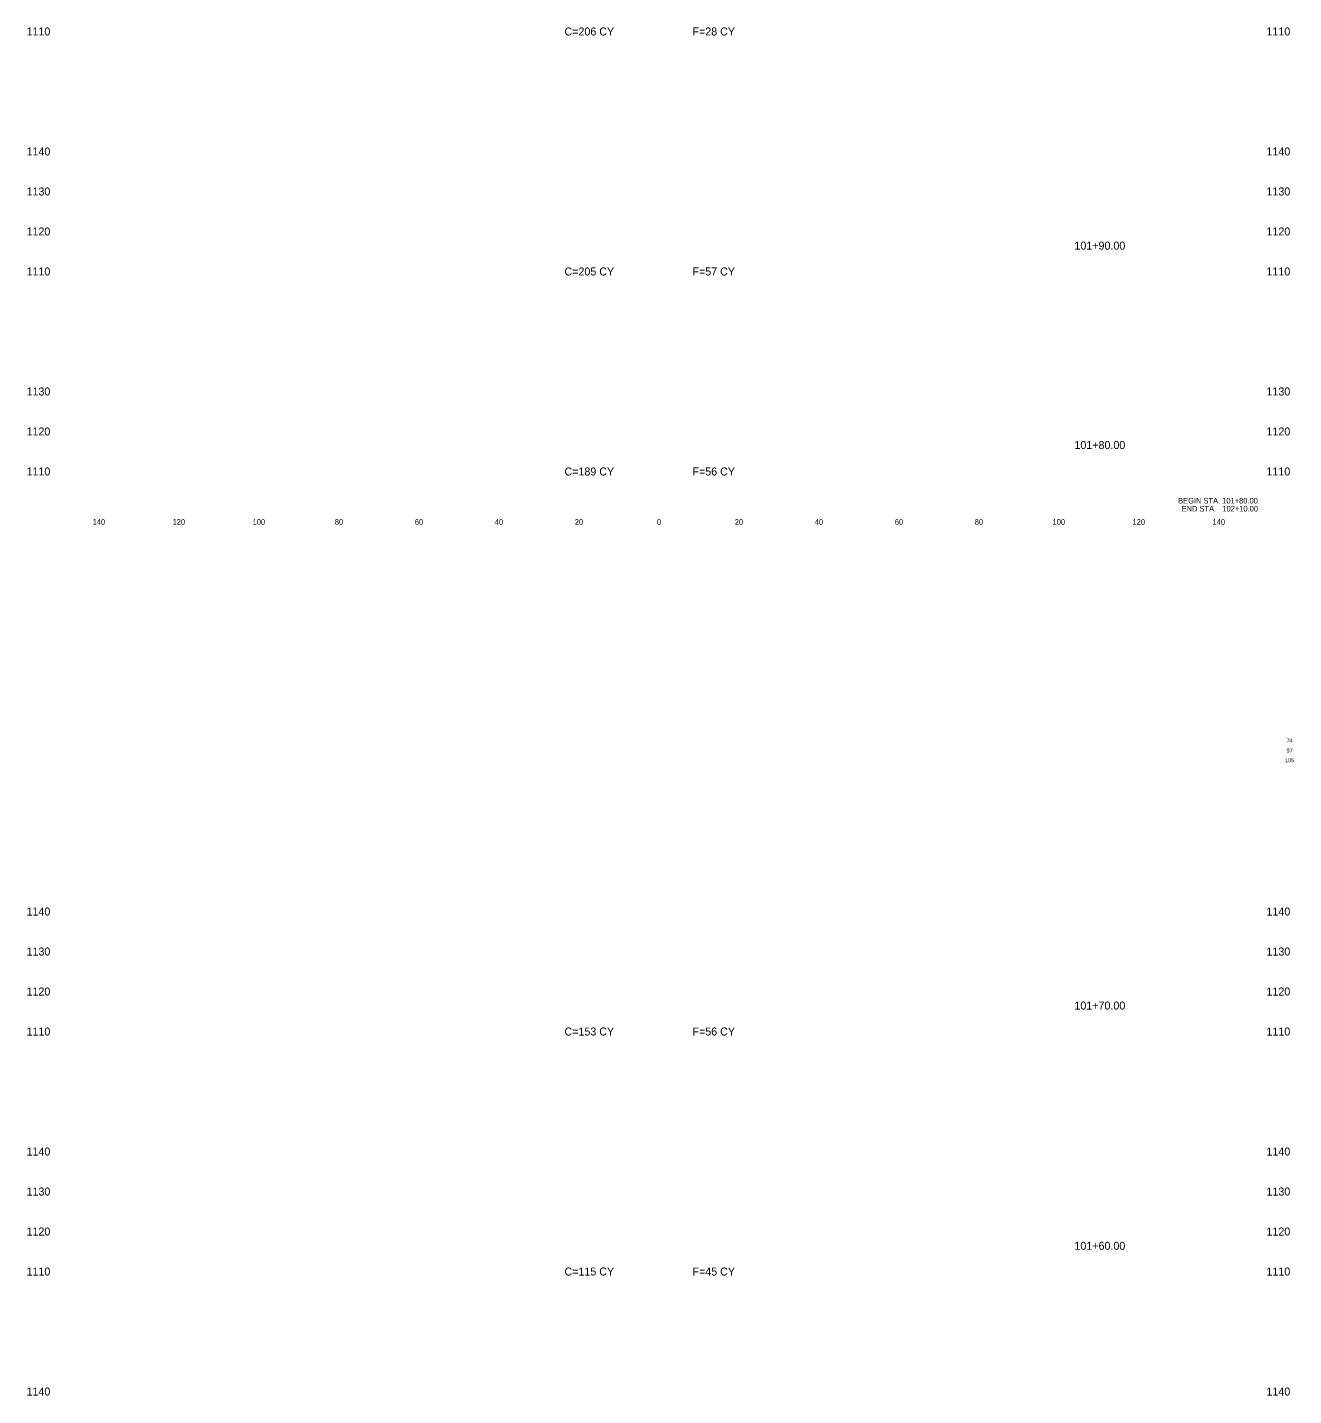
# Model space of a CAD drawing. Extents: x -200 to 1319, y -200 to 2499.
# Drawn here: x 1001.9 to 1318.5, y 1820 to 2162 of the extents above; entities that cross this region are included whole.
import ezdxf

# ---------------------------------------------------------------- set-up
doc = ezdxf.new("R2010")
doc.units = 0
for name, color, linetype in [('Default', 7, 'Continuous'), ('DESIGN - SHEET - Corner Text', 7, 'Continuous'), ('DESIGN - TYPICAL - Text', 7, 'Continuous')]:
    doc.layers.add(name, color=color, linetype=linetype)

msp = doc.modelspace()

# ---------------------------------------------------------------- texts
at = {"layer": 'Default'}
for s, height, p in [('     1110     ', 2, (998.01, 2160)), ('     1110     ', 2, (1308.01, 2160)), ('     1140     ', 2, (998.01, 2130)), ('     1140     ', 2, (1308.01, 2130)), ('     1130     ', 2, (998.01, 2120)), ('     1130     ', 2, (1308.01, 2120)), ('     1120     ', 2, (998.01, 2110)), ('     1120     ', 2, (1308.01, 2110)), ('     101+90.00     ', 2, (1260, 2106.47)), ('     1110     ', 2, (998.01, 2100)), ('     1110     ', 2, (1308.01, 2100)), ('     1130     ', 2, (998.01, 2070)), ('     1130     ', 2, (1308.01, 2070)), ('     1120     ', 2, (998.01, 2060)), ('     1120     ', 2, (1308.01, 2060)), ('     101+80.00     ', 2, (1260, 2056.62)), ('     1110     ', 2, (998.01, 2050)), ('     1110     ', 2, (1308.01, 2050)), ('     140     ', 1.4, (1015.65, 2037.7)), ('     120     ', 1.4, (1035.65, 2037.7)), ('     100     ', 1.4, (1055.65, 2037.7)), ('     80     ', 1.4, (1076.2, 2037.7)), ('     60     ', 1.4, (1096.2, 2037.7)), ('     40     ', 1.4, (1116.2, 2037.7)), ('     20     ', 1.4, (1136.2, 2037.7)), ('     0     ', 1.4, (1156.74, 2037.7)), ('     0     ', 1.4, (1156.74, 2037.7)), ('     20     ', 1.4, (1176.2, 2037.7)), ('     40     ', 1.4, (1196.2, 2037.7)), ('     60     ', 1.4, (1216.2, 2037.7)), ('     80     ', 1.4, (1236.2, 2037.7)), ('     100     ', 1.4, (1255.65, 2037.7)), ('     120     ', 1.4, (1275.65, 2037.7)), ('     140     ', 1.4, (1295.65, 2037.7)), ('     1140     ', 2, (998.01, 1940)), ('     1140     ', 2, (1308.01, 1940)), ('     1130     ', 2, (998.01, 1930)), ('     1130     ', 2, (1308.01, 1930)), ('     1120     ', 2, (998.01, 1920)), ('     1120     ', 2, (1308.01, 1920)), ('     101+70.00     ', 2, (1260, 1916.49)), ('     1110     ', 2, (998.01, 1910)), ('     1110     ', 2, (1308.01, 1910)), ('     1140     ', 2, (998.01, 1880)), ('     1140     ', 2, (1308.01, 1880)), ('     1130     ', 2, (998.01, 1870)), ('     1130     ', 2, (1308.01, 1870)), ('     1120     ', 2, (998.01, 1860)), ('     1120     ', 2, (1308.01, 1860)), ('     101+60.00     ', 2, (1260, 1856.43)), ('     1110     ', 2, (998.01, 1850)), ('     1110     ', 2, (1308.01, 1850)), ('     1140     ', 2, (998.01, 1820)), ('     1140     ', 2, (1308.01, 1820))]:
    msp.add_text(s, height=height, dxfattribs=at).set_placement(p)
at = {"layer": 'DESIGN - SHEET - Corner Text'}
for s, height, p in [('BEGIN STA. 101+80.00', 1.4, (1289.64, 2043)), ('END STA.   102+10.00', 1.4, (1290.51, 2041)), ('74', 1, (1316.76, 1983.25)), ('97', 1, (1316.75, 1980.75)), ('105', 1, (1316.35, 1978.31))]:
    msp.add_text(s, height=height, dxfattribs=at).set_placement(p)
at = {"layer": 'DESIGN - TYPICAL - Text'}
for s, p in [('C=206 CY', (1136.22, 2160)), ('F=28 CY', (1168.22, 2160)), ('C=205 CY', (1136.22, 2100)), ('F=57 CY', (1168.22, 2100)), ('C=189 CY', (1136.22, 2050)), ('F=56 CY', (1168.22, 2050)), ('C=153 CY', (1136.22, 1910)), ('F=56 CY', (1168.22, 1910)), ('C=115 CY', (1136.22, 1850)), ('F=45 CY', (1168.22, 1850))]:
    msp.add_text(s, height=2, dxfattribs=at).set_placement(p)

doc.saveas('drawing.dxf')
